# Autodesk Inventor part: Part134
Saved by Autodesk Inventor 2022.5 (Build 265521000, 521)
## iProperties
Created: 2024-12
Part Number: Part134
Material: Generic
Document SubType Name: Modeling
Designer: AdminForWorker
Density: 1 g/cm^3
Appearance: Default
Author: AdminForWorker
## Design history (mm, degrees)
feature "Body1"
feature "Body2"
feature "Body3"
body "Solid1"
body "Solid2"
body "Solid3"
